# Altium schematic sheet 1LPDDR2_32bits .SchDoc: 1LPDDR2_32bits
size A3; Date: Not used; ApprovedBy: Not used; CheckedBy: Not used; Author: Not used; CompanyName: STMicroelectronics; DrawnBy: Not used; Engineer: Not used; Organization: Not used; Address1: Not used; Address2: Not used; Address3: Not used; Address4: Not used; DocumentNumber: Not used; Revision: Not used; SheetNumber: 7; SheetTotal: 7
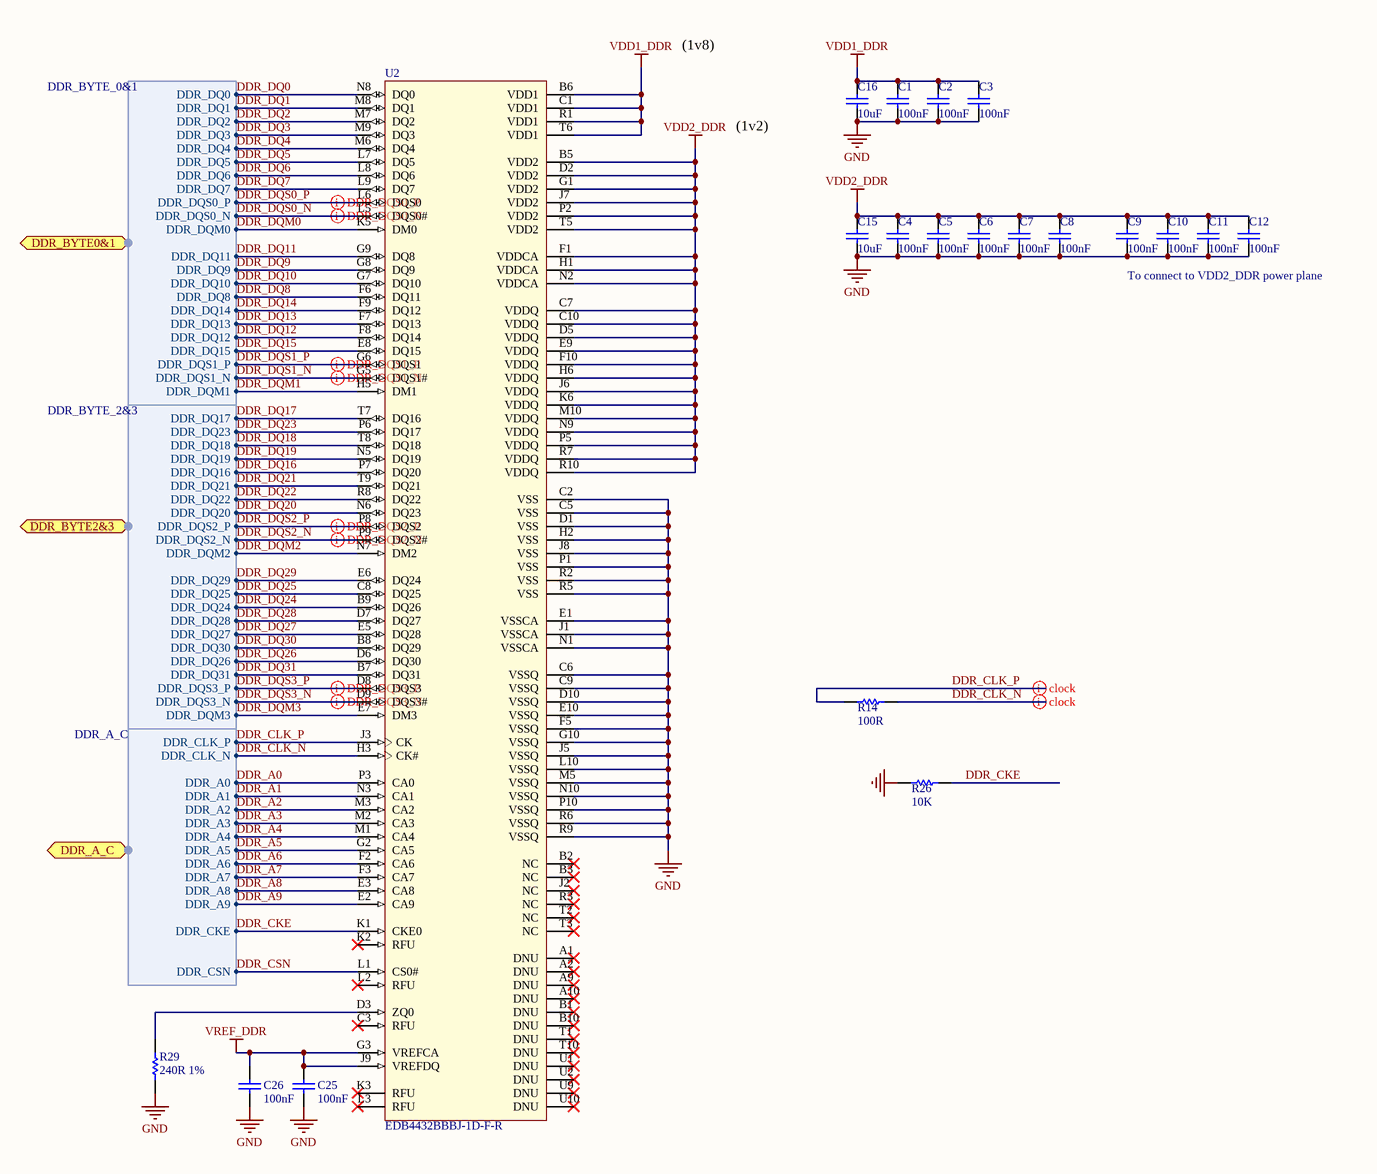
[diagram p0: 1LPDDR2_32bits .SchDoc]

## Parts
C1  value 100nF  [C0402]
C2  value 100nF  [C0402]
C3  value 100nF  [C0402]
C4  value 100nF  [C0402]
C5  value 100nF  [C0402]
C6  value 100nF  [C0402]
C7  value 100nF  [C0402]
C8  value 100nF  [C0402]
C9  value 100nF  [C0402]
C10  value 100nF  [C0402]
C11  value 100nF  [C0402]
C12  value 100nF  [C0402]
C15  value 10uF  [C0603]
C16  value 10uF  [C0603]
C25  value 100nF  [C0402]
C26  value 100nF  [C0402]
R14  value 100R  [R0402]
R26  value 10K  [R0402]
R29  value 240R 1%  [R0402]
U2  value EDB4432BBBJ-1D-F-R  [ICC_WFBGA134_SDP-SAC302_10X11P5_P065]

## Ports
DDR_A_C (harness DDR_A_C), DDR_BYTE0&1 (harness DDR_BYTE_0&1), DDR_BYTE2&3 (harness DDR_BYTE_2&3)

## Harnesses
DDR_BYTE_0&1: DDR_DQ0, DDR_DQ1, DDR_DQ2, DDR_DQ3, DDR_DQ4, DDR_DQ5, DDR_DQ6, DDR_DQ7, DDR_DQS0_P, DDR_DQS0_N, DDR_DQM0, DDR_DQ11, DDR_DQ9, DDR_DQ10, DDR_DQ8, DDR_DQ14, DDR_DQ13, DDR_DQ12, DDR_DQ15, DDR_DQS1_P, DDR_DQS1_N, DDR_DQM1
DDR_BYTE_2&3: DDR_DQ16, DDR_DQ17, DDR_DQ18, DDR_DQ23, DDR_DQ22, DDR_DQ19, DDR_DQ21, DDR_DQ20, DDR_DQS2_P, DDR_DQS2_N, DDR_DQ24, DDR_DQM2, DDR_DQ29, DDR_DQ27, DDR_DQ25, DDR_DQ28, DDR_DQ30, DDR_DQ26, DDR_DQ31, DDR_DQS3_P, DDR_DQS3_N, DDR_DQM3
DDR_A_C: DDR_CLK_P, DDR_CLK_N, DDR_A0, DDR_A1, DDR_A2, DDR_A3, DDR_A4, DDR_A5, DDR_A6, DDR_A7, DDR_A8, DDR_A9, DDR_CSN, DDR_CKE

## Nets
GND: C1.2 C2.2 C3.2 C4.2 C5.2 C6.2 C7.2 C8.2 C9.2 C10.2 C11.2 C12.2 C15.1 C16.1 C25.2 C26.2 R26.1 R29.1 U2.C2(VSS) U2.C5(VSS) U2.C6(VSSQ) U2.C9(VSSQ) U2.D1(VSS) U2.D10(VSSQ) U2.E1(VSSCA) U2.E10(VSSQ) U2.F5(VSSQ) U2.G10(VSSQ) U2.H2(VSS) U2.J1(VSSCA) U2.J5(VSSQ) U2.J8(VSS) U2.L10(VSSQ) U2.M5(VSSQ) U2.N1(VSSCA) U2.N10(VSSQ) U2.P1(VSS) U2.P10(VSSQ) U2.R2(VSS) U2.R5(VSS) U2.R6(VSSQ) U2.R9(VSSQ)
VDD1_DDR: C1.1 C2.1 C3.1 C16.2 U2.B6(VDD1) U2.C1(VDD1) U2.R1(VDD1) U2.T6(VDD1)
VDD2_DDR: C4.1 C5.1 C6.1 C7.1 C8.1 C9.1 C10.1 C11.1 C12.1 C15.2 U2.B5(VDD2) U2.C7(VDDQ) U2.C10(VDDQ) U2.D2(VDD2) U2.D5(VDDQ) U2.E9(VDDQ) U2.F1(VDDCA) U2.F10(VDDQ) U2.G1(VDD2) U2.H1(VDDCA) U2.H6(VDDQ) U2.J6(VDDQ) U2.J7(VDD2) U2.K6(VDDQ) U2.M10(VDDQ) U2.N2(VDDCA) U2.N9(VDDQ) U2.P2(VDD2) U2.P5(VDDQ) U2.R7(VDDQ) U2.R10(VDDQ) U2.T5(VDD2)
VREF_DDR: C25.1 C26.1 U2.G3(VREFCA) U2.J9(VREFDQ)
DDR_A0: U2.P3(CA0) ; port DDR_A_C.DDR_A0
DDR_A1: U2.N3(CA1) ; port DDR_A_C.DDR_A1
DDR_A2: U2.M3(CA2) ; port DDR_A_C.DDR_A2
DDR_A3: U2.M2(CA3) ; port DDR_A_C.DDR_A3
DDR_A4: U2.M1(CA4) ; port DDR_A_C.DDR_A4
DDR_A5: U2.G2(CA5) ; port DDR_A_C.DDR_A5
DDR_A6: U2.F2(CA6) ; port DDR_A_C.DDR_A6
DDR_A7: U2.F3(CA7) ; port DDR_A_C.DDR_A7
DDR_A8: U2.E3(CA8) ; port DDR_A_C.DDR_A8
DDR_A9: U2.E2(CA9) ; port DDR_A_C.DDR_A9
DDR_CKE: R26.2 U2.K1(CKE0) ; port DDR_A_C.DDR_CKE
DDR_CLK_N: R14.2 U2.H3(CK#) ; port DDR_A_C.DDR_CLK_N
DDR_CLK_P: R14.1 U2.J3(CK) ; port DDR_A_C.DDR_CLK_P
DDR_CSN: U2.L1(CS0#) ; port DDR_A_C.DDR_CSN
DDR_DQ0: U2.N8(DQ0) ; port DDR_BYTE0&1.DDR_DQ0
DDR_DQ1: U2.M8(DQ1) ; port DDR_BYTE0&1.DDR_DQ1
DDR_DQ2: U2.M7(DQ2) ; port DDR_BYTE0&1.DDR_DQ2
DDR_DQ3: U2.M9(DQ3) ; port DDR_BYTE0&1.DDR_DQ3
DDR_DQ4: U2.M6(DQ4) ; port DDR_BYTE0&1.DDR_DQ4
DDR_DQ5: U2.L7(DQ5) ; port DDR_BYTE0&1.DDR_DQ5
DDR_DQ6: U2.L8(DQ6) ; port DDR_BYTE0&1.DDR_DQ6
DDR_DQ7: U2.L9(DQ7) ; port DDR_BYTE0&1.DDR_DQ7
DDR_DQ8: U2.F6(DQ11) ; port DDR_BYTE0&1.DDR_DQ8
DDR_DQ9: U2.G8(DQ9) ; port DDR_BYTE0&1.DDR_DQ9
DDR_DQ10: U2.G7(DQ10) ; port DDR_BYTE0&1.DDR_DQ10
DDR_DQ11: U2.G9(DQ8) ; port DDR_BYTE0&1.DDR_DQ11
DDR_DQ12: U2.F8(DQ14) ; port DDR_BYTE0&1.DDR_DQ12
DDR_DQ13: U2.F7(DQ13) ; port DDR_BYTE0&1.DDR_DQ13
DDR_DQ14: U2.F9(DQ12) ; port DDR_BYTE0&1.DDR_DQ14
DDR_DQ15: U2.E8(DQ15) ; port DDR_BYTE0&1.DDR_DQ15
DDR_DQ16: U2.P7(DQ20) ; port DDR_BYTE2&3.DDR_DQ16
DDR_DQ17: U2.T7(DQ16) ; port DDR_BYTE2&3.DDR_DQ17
DDR_DQ18: U2.T8(DQ18) ; port DDR_BYTE2&3.DDR_DQ18
DDR_DQ19: U2.N5(DQ19) ; port DDR_BYTE2&3.DDR_DQ19
DDR_DQ20: U2.N6(DQ23) ; port DDR_BYTE2&3.DDR_DQ20
DDR_DQ21: U2.T9(DQ21) ; port DDR_BYTE2&3.DDR_DQ21
DDR_DQ22: U2.R8(DQ22) ; port DDR_BYTE2&3.DDR_DQ22
DDR_DQ23: U2.P6(DQ17) ; port DDR_BYTE2&3.DDR_DQ23
DDR_DQ24: U2.B9(DQ26) ; port DDR_BYTE2&3.DDR_DQ24
DDR_DQ25: U2.C8(DQ25) ; port DDR_BYTE2&3.DDR_DQ25
DDR_DQ26: U2.D6(DQ30) ; port DDR_BYTE2&3.DDR_DQ26
DDR_DQ27: U2.E5(DQ28) ; port DDR_BYTE2&3.DDR_DQ27
DDR_DQ28: U2.D7(DQ27) ; port DDR_BYTE2&3.DDR_DQ28
DDR_DQ29: U2.E6(DQ24) ; port DDR_BYTE2&3.DDR_DQ29
DDR_DQ30: U2.B8(DQ29) ; port DDR_BYTE2&3.DDR_DQ30
DDR_DQ31: U2.B7(DQ31) ; port DDR_BYTE2&3.DDR_DQ31
DDR_DQM0: U2.K5(DM0) ; port DDR_BYTE0&1.DDR_DQM0
DDR_DQM1: U2.H5(DM1) ; port DDR_BYTE0&1.DDR_DQM1
DDR_DQM2: U2.N7(DM2) ; port DDR_BYTE2&3.DDR_DQM2
DDR_DQM3: U2.E7(DM3) ; port DDR_BYTE2&3.DDR_DQM3
DDR_DQS0_N: U2.L5(DQS0#) ; port DDR_BYTE0&1.DDR_DQS0_N
DDR_DQS0_P: U2.L6(DQS0) ; port DDR_BYTE0&1.DDR_DQS0_P
DDR_DQS1_N: U2.G5(DQS1#) ; port DDR_BYTE0&1.DDR_DQS1_N
DDR_DQS1_P: U2.G6(DQS1) ; port DDR_BYTE0&1.DDR_DQS1_P
DDR_DQS2_N: U2.P9(DQS2#) ; port DDR_BYTE2&3.DDR_DQS2_N
DDR_DQS2_P: U2.P8(DQS2) ; port DDR_BYTE2&3.DDR_DQS2_P
DDR_DQS3_N: U2.D9(DQS3#) ; port DDR_BYTE2&3.DDR_DQS3_N
DDR_DQS3_P: U2.D8(DQS3) ; port DDR_BYTE2&3.DDR_DQS3_P
NetR29_2: R29.2 U2.D3(ZQ0)

Not connected (* = marked no-connect by the designer): U2 A1(DNU)* A2(DNU)* A9(DNU)* A10(DNU)* B1(DNU)* B2(NC)* B3(NC)* B10(DNU)* C3(RFU)* J2(NC)* K2(RFU)* K3(RFU)* L2(RFU)* L3(RFU)* R3(NC)* T1(DNU)* T2(NC)* T3(NC)* T10(DNU)* U1(DNU)* U2(DNU)* U9(DNU)* U10(DNU)*

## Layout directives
differential pair: DDR_CLK_N, DDR_CLK_P, DDR_DQS0_N, DDR_DQS0_P, DDR_DQS1_N, DDR_DQS1_P, DDR_DQS2_N, DDR_DQS2_P, DDR_DQS3_N, DDR_DQS3_P

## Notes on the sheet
- (1v8)
- (1v2)
- To connect to VDD2_DDR power plane

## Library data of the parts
C1-C12 C25 C26 = MCD-00006: Capacitor, MLCC, 100nF, 16V, X7R, 10%, 0402, T=0.5mm; Manufacturer_Part_Number: CC0402KRX7R7BB104; Manufacturer: YAGEO; Alternate_Manufacturer_Part_Number: GCM155R71C104KA55D; Alternate_Manufacturer: MURATA; Provided_By: SUBCO; ECCN_US: EAR99; ECCN_EU: NEC
C15 C16 = MCD-01124: Capacitor, MLCC, 10uF, 10V, X5R, 10%, 0603, T=0.8mm; Manufacturer_Part_Number: GRM188R61A106KAAL; Manufacturer: MURATA; Provided_By: SUBCO; ECCN_US: EAR99; ECCN_EU: NEC
R14 = MCD-00067: Resistor,100R,0402,1%,1/16W; Manufacturer_Part_Number: RC0402FR-07100RL; Manufacturer: YAGEO; Provided_By: SUBCO; ECCN_US: EAR99; ECCN_EU: NEC
R26 = MCD-00053: Resistor,10K,0402,1%,1/16W; Manufacturer_Part_Number: RC0402FR-0710KL; Manufacturer: YAGEO; BMS_Part_Number: 9131590; Provided_By: SUBCO; ECCN_US: EAR99; ECCN_EU: NEC
R29 = MCD-00120: Resistor,240R,0402,1%,1/16W; Manufacturer_Part_Number: RC0402FR-07240RL; Manufacturer: YAGEO; ECCN_US: EAR99; ECCN_EU: NEC; Provided_By: SUBCO
U2 = MCD-01223: Memory,LPDDR2,4Gb,128Mbx32,533MHz,1066Mb/s,1V8/1V2,FBGA134; Part_Type: IC; Manufacturer: MICRON; Provided_By: SUBCO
